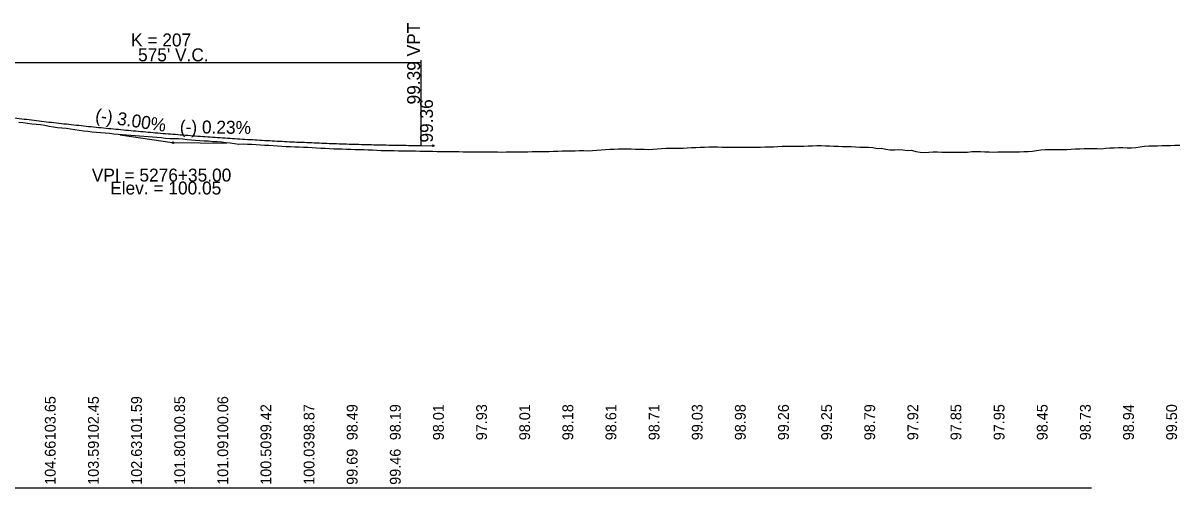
# Model space of a CAD drawing. Extents: x 2121671 to 2169879, y 557274 to 599957.
# Drawn here: x 2157029 to 2158371, y 595707 to 596246 of the extents above; entities that cross this region are included whole.
import ezdxf

# ---------------------------------------------------------------- set-up
doc = ezdxf.new("R2010")
doc.units = 0
for name, color, linetype in [('RD_DDB_GradeTX', 7, 'Continuous'), ('RD_DDB_Profile_EX', 7, 'Continuous'), ('RD_DDB_Profile_Lbl', 7, 'Continuous'), ('RD_DDB_Profile_PR', 7, 'Continuous'), ('RD_DDB_StripGrade', 7, 'Continuous'), ('RD_DDB_VCLbl', 7, 'Continuous'), ('RD_GPK_Profile_Cell', 7, 'Continuous')]:
    doc.layers.add(name, color=color, linetype=linetype)

msp = doc.modelspace()

# ---------------------------------------------------------------- linework, layer by layer
at = {"layer": 'RD_DDB_GradeTX'}
for p, q in [((2157141.9, 596116.9), (2157202.3, 596107.9)), ((2157265.2, 596107), (2157204.2, 596107.7))]:
    msp.add_line(p, q, dxfattribs=at)
for centre in [(2157203.2, 596107.7), (2157504.8, 596104.3)]:
    msp.add_circle(centre, 1, dxfattribs=at)
at = {"layer": 'RD_DDB_Profile_EX'}
for points in [[(2157024.5, 596131.6), (2157029.5, 596131), (2157034.5, 596130.3), (2157039.5, 596129.8), (2157044.5, 596129.3), (2157049.5, 596128.8), (2157054.5, 596127.9), (2157059.5, 596127.1), (2157064.5, 596126.3), (2157069.5, 596125.5), (2157074.5, 596125), (2157079.5, 596124.7), (2157084.5, 596123.8), (2157089.5, 596123.1), (2157094.5, 596122.4), (2157099.5, 596121.7), (2157104.5, 596121), (2157109.5, 596120.3), (2157114.5, 596119.9), (2157119.5, 596119.7), (2157124.5, 596119.2), (2157129.5, 596118.7), (2157134.5, 596118.2), (2157139.5, 596117.7), (2157144.5, 596117.3), (2157149.5, 596116.8), (2157154.5, 596116.4), (2157159.5, 596116), (2157164.5, 596115.7), (2157169.5, 596115.3), (2157174.5, 596114.9), (2157179.5, 596114.5), (2157184.5, 596114.1), (2157189.5, 596113.6), (2157194.5, 596113.1)], [(2157194.5, 596113.1), (2157199.5, 596112.7), (2157204.5, 596112.7), (2157209.5, 596112.5), (2157214.5, 596112.1), (2157219.5, 596111.6), (2157224.5, 596111.2), (2157229.5, 596110.7), (2157234.5, 596110.4), (2157239.5, 596110.1), (2157244.5, 596109.8), (2157249.5, 596109.3), (2157254.5, 596109), (2157259.5, 596108.6), (2157264.5, 596108.1), (2157269.5, 596107.6), (2157274.5, 596106.8), (2157279.5, 596106.2), (2157284.5, 596106.3), (2157289.5, 596106.2), (2157294.5, 596105.9), (2157299.5, 596105.5), (2157304.5, 596105.3), (2157309.5, 596105), (2157314.5, 596104.8), (2157319.5, 596104.5), (2157324.5, 596104.2), (2157329.5, 596103.8), (2157334.5, 596103.5), (2157339.5, 596103.2), (2157344.5, 596103.1), (2157349.5, 596102.9), (2157354.5, 596102.7), (2157359.5, 596102.4), (2157364.5, 596102), (2157369.5, 596101.7), (2157374.5, 596101.5), (2157379.5, 596101.3), (2157384.5, 596101), (2157389.5, 596100.7), (2157394.5, 596100.6), (2157399.5, 596100.5), (2157404.5, 596100.2), (2157409.5, 596100.1), (2157414.5, 596100), (2157419.5, 596099.9), (2157424.5, 596099.8), (2157429.5, 596099.5), (2157434.5, 596099.3), (2157439.5, 596099.1), (2157444.5, 596098.9), (2157449.5, 596098.9), (2157454.5, 596098.8), (2157459.5, 596098.7), (2157464.5, 596098.5), (2157469.5, 596098.4), (2157474.5, 596098.4), (2157479.5, 596098.3), (2157484.5, 596098.2), (2157489.5, 596098), (2157494.5, 596097.9), (2157499.5, 596097.9), (2157504.5, 596097.9), (2157509.5, 596097.7), (2157514.5, 596097.6), (2157519.5, 596097.5), (2157524.5, 596097.5), (2157529.5, 596097.5), (2157534.5, 596097.5), (2157539.5, 596097.3), (2157544.5, 596097.3), (2157549.5, 596097.3), (2157554.5, 596097.2), (2157559.5, 596097.2), (2157564.5, 596097.2), (2157569.5, 596097.1), (2157574.5, 596097), (2157579.5, 596097), (2157584.5, 596096.9), (2157589.5, 596097), (2157594.5, 596097), (2157599.5, 596097), (2157604.5, 596097.1), (2157609.5, 596097.2), (2157614.5, 596097.3), (2157619.5, 596097.6), (2157624.5, 596097.6), (2157629.5, 596097.6), (2157634.5, 596097.6), (2157639.5, 596097.7), (2157644.5, 596097.8), (2157649.5, 596097.9), (2157654.5, 596098.3), (2157659.5, 596098.4), (2157664.5, 596098.3), (2157669.5, 596098.4), (2157674.5, 596098.6), (2157679.5, 596098.6), (2157684.5, 596098.5), (2157689.5, 596098.9), (2157694.5, 596099.2)], [(2157694.5, 596099.2), (2157699.5, 596099.6), (2157704.5, 596099.9), (2157709.5, 596100.3), (2157714.5, 596100.4), (2157719.5, 596100.5), (2157724.5, 596100.7), (2157729.5, 596100.7), (2157734.5, 596100.6), (2157739.5, 596100.4), (2157744.5, 596100.4), (2157749.5, 596100.2), (2157754.5, 596099.9), (2157759.5, 596100.2), (2157764.5, 596100.7), (2157769.5, 596101.1), (2157774.5, 596101.4), (2157779.5, 596101.4), (2157784.5, 596101.3), (2157789.5, 596101.4), (2157794.5, 596101.5), (2157799.5, 596101.8), (2157804.5, 596102.1), (2157809.5, 596102.3), (2157814.5, 596102.5), (2157819.5, 596102.7), (2157824.5, 596102.9), (2157829.5, 596102.9), (2157834.5, 596102.9), (2157839.5, 596102.7), (2157844.5, 596102.6), (2157849.5, 596102.6), (2157854.5, 596102.5), (2157859.5, 596102.4), (2157864.5, 596102.4), (2157869.5, 596102.4), (2157874.5, 596102.5), (2157879.5, 596102.5), (2157884.5, 596102.7), (2157889.5, 596102.8), (2157894.5, 596102.9), (2157899.5, 596102.9), (2157904.5, 596103.2), (2157909.5, 596103.6), (2157914.5, 596103.7), (2157919.5, 596103.8), (2157924.5, 596103.9), (2157929.5, 596103.9), (2157934.5, 596103.9), (2157939.5, 596104), (2157944.5, 596104.1), (2157949.5, 596104.4), (2157954.5, 596104.5), (2157959.5, 596104.3), (2157964.5, 596104), (2157969.5, 596103.6), (2157974.5, 596103.6), (2157979.5, 596103.4), (2157984.5, 596103.5), (2157989.5, 596103.4), (2157994.5, 596103), (2157999.5, 596102.7), (2158004.5, 596102.7), (2158009.5, 596102.6), (2158014.5, 596102.1), (2158019.5, 596101.2), (2158024.5, 596101.3), (2158029.5, 596100.4), (2158034.5, 596099.6), (2158039.5, 596099.5), (2158044.5, 596100), (2158049.5, 596099.5), (2158054.5, 596098.9), (2158059.5, 596099.1), (2158064.5, 596097.7), (2158069.5, 596096.9), (2158074.5, 596096.5), (2158079.5, 596096.9), (2158084.5, 596097.3), (2158089.5, 596097.2), (2158094.5, 596096.7), (2158099.5, 596096.8), (2158104.5, 596096.8), (2158109.5, 596096.7), (2158114.5, 596096.9), (2158119.5, 596096.7), (2158124.5, 596096.8), (2158129.5, 596097.5), (2158134.5, 596097.5), (2158139.5, 596097.4), (2158144.5, 596097.2), (2158149.5, 596097.1), (2158154.5, 596096.8), (2158159.5, 596097), (2158164.5, 596097.1), (2158169.5, 596097.2), (2158174.5, 596097.3), (2158179.5, 596097), (2158184.5, 596097.3), (2158189.5, 596097.6), (2158194.5, 596097.7)], [(2158194.5, 596097.7), (2158199.5, 596098), (2158204.5, 596098.6), (2158209.5, 596099.4), (2158214.5, 596099.7), (2158219.5, 596099.8), (2158224.5, 596099.8), (2158229.5, 596099.8), (2158234.5, 596099.8), (2158239.5, 596099.8), (2158244.5, 596100.2), (2158249.5, 596100.5), (2158254.5, 596100.8), (2158259.5, 596101), (2158264.5, 596101.1), (2158269.5, 596101.1), (2158274.5, 596101), (2158279.5, 596100.8), (2158284.5, 596101.3), (2158289.5, 596101.7), (2158294.5, 596101.9), (2158299.5, 596102.2), (2158304.5, 596102), (2158309.5, 596101.9), (2158314.5, 596101.9), (2158319.5, 596102.3), (2158324.5, 596103), (2158329.5, 596103.6), (2158334.5, 596104), (2158339.5, 596104), (2158344.5, 596104.3), (2158349.5, 596104.4), (2158354.5, 596104.5), (2158359.5, 596104.6), (2158364.5, 596104.8), (2158369.5, 596105), (2158370.5, 596105)]]:
    msp.add_lwpolyline(points, dxfattribs=at)
at = {"layer": 'RD_DDB_Profile_PR'}
msp.add_line((2157490.7, 596104.4), (2157504.8, 596104.3), dxfattribs=at)
msp.add_spline([(2156915.7, 596150.8), (2156927.2, 596149.1), (2156938.7, 596147.4), (2156950.2, 596145.8), (2156961.7, 596144.2), (2156973.2, 596142.6), (2156984.7, 596141.1), (2156996.2, 596139.5), (2157007.7, 596138.1), (2157019.2, 596136.6), (2157030.7, 596135.2), (2157042.2, 596133.8), (2157053.7, 596132.4), (2157065.2, 596131.1), (2157076.7, 596129.8), (2157088.2, 596128.5), (2157099.7, 596127.3), (2157111.2, 596126.1), (2157122.7, 596124.9), (2157134.2, 596123.8), (2157145.7, 596122.7), (2157157.2, 596121.6), (2157168.7, 596120.6), (2157180.2, 596119.6), (2157191.7, 596118.6), (2157203.2, 596117.7), (2157214.7, 596116.8), (2157226.2, 596115.9), (2157237.7, 596115), (2157249.2, 596114.2), (2157260.7, 596113.4), (2157272.2, 596112.7), (2157283.7, 596112), (2157295.2, 596111.3), (2157306.7, 596110.6), (2157318.2, 596110), (2157329.7, 596109.4), (2157341.2, 596108.8), (2157352.7, 596108.3), (2157364.2, 596107.8), (2157375.7, 596107.3), (2157387.2, 596106.9), (2157398.7, 596106.5), (2157410.2, 596106.1), (2157421.7, 596105.8), (2157433.2, 596105.5), (2157444.7, 596105.2), (2157456.2, 596105), (2157467.7, 596104.8), (2157479.2, 596104.6), (2157490.7, 596104.4)], degree=3, dxfattribs=at)
at = {"layer": 'RD_DDB_VCLbl'}
for p, q in [((2156915.7, 596200.8), (2157490.7, 596200.8)), ((2157490.7, 596203.3), (2157490.7, 596104.4))]:
    msp.add_line(p, q, dxfattribs=at)
at = {"layer": 'RD_GPK_Profile_Cell'}
msp.add_line((2151068.2, 595707.5), (2158268.2, 595707.5), dxfattribs=at)
msp.add_line((2151068.2, 595707.5), (2158268.2, 595707.5), dxfattribs=at)

# ---------------------------------------------------------------- texts
at = {"layer": 'RD_DDB_GradeTX'}
for s, rotation, p in [('(-) 3.00%', 351.4692, (2157112.4, 596132.6)), ('(-) 0.23%', 359.3498, (2157211.1, 596118.8))]:
    msp.add_text(s, height=15, rotation=rotation, dxfattribs=at).set_placement(p)
at = {"layer": 'RD_DDB_Profile_Lbl'}
msp.add_text('99.36', height=15, rotation=90, dxfattribs=at).set_placement((2157504.6, 596107.9))
for s, p in [('VPI = 5276+35.00', (2157109.1, 596062.7)), ('Elev. = 100.05', (2157130.4, 596047.7))]:
    msp.add_text(s, height=15, dxfattribs=at).set_placement(p)
at = {"layer": 'RD_DDB_StripGrade'}
for s, height, p in [('99.39 VPT', 15, (2157489.7, 596152.1)), ('103.65', 12.5, (2157067.2, 595762.7)), ('102.45', 12.5, (2157117.2, 595762.7)), ('101.59', 12.5, (2157167.2, 595762.7)), ('100.85', 12.5, (2157217.2, 595762.7)), ('100.06', 12.5, (2157267.2, 595762.7)), ('99.42', 12.5, (2157317.2, 595762.7)), ('98.87', 12.5, (2157367.2, 595762.7)), ('98.49', 12.5, (2157417.2, 595762.7)), ('98.19', 12.5, (2157467.2, 595762.7)), ('98.01', 12.5, (2157517.2, 595762.7)), ('97.93', 12.5, (2157567.2, 595762.7)), ('98.01', 12.5, (2157617.2, 595762.7)), ('98.18', 12.5, (2157667.2, 595762.7)), ('98.61', 12.5, (2157717.2, 595762.7)), ('98.71', 12.5, (2157767.2, 595762.7)), ('99.03', 12.5, (2157817.2, 595762.7)), ('98.98', 12.5, (2157867.2, 595762.7)), ('99.26', 12.5, (2157917.2, 595762.7)), ('99.25', 12.5, (2157967.2, 595762.7)), ('98.79', 12.5, (2158017.2, 595762.7)), ('97.92', 12.5, (2158067.2, 595762.7)), ('97.85', 12.5, (2158117.2, 595762.7)), ('97.95', 12.5, (2158167.2, 595762.7)), ('98.45', 12.5, (2158217.2, 595762.7)), ('98.73', 12.5, (2158267.2, 595762.7)), ('98.94', 12.5, (2158317.2, 595762.7)), ('99.50', 12.5, (2158367.2, 595762.7)), ('104.66', 12.5, (2157067.2, 595711)), ('103.59', 12.5, (2157117.2, 595711)), ('102.63', 12.5, (2157167.2, 595711)), ('101.80', 12.5, (2157217.2, 595711)), ('101.09', 12.5, (2157267.2, 595711)), ('100.50', 12.5, (2157317.2, 595711)), ('100.03', 12.5, (2157367.2, 595711)), ('99.69', 12.5, (2157417.2, 595711)), ('99.46', 12.5, (2157467.2, 595711))]:
    msp.add_text(s, height=height, rotation=90, dxfattribs=at).set_placement(p)
at = {"layer": 'RD_DDB_VCLbl'}
for s, p in [('K = 207', (2157154.6, 596219.4)), ("575' V.C.", (2157162.7, 596202.1))]:
    msp.add_text(s, height=15, dxfattribs=at).set_placement(p)

doc.saveas('drawing.dxf')
